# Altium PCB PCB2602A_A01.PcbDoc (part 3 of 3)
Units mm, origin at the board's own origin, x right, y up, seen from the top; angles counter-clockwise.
Board outline 30.4 x 45.4 mm, 8 copper layers (Top Layer, Signal Layer 2, Signal Layer 3, Signal Layer 4, Signal Layer 5, Signal Layer 6, Signal Layer 7, Bottom Layer), stack 1.594 mm thick; 180 components, 124 nets, 679 pads, 487 vias.
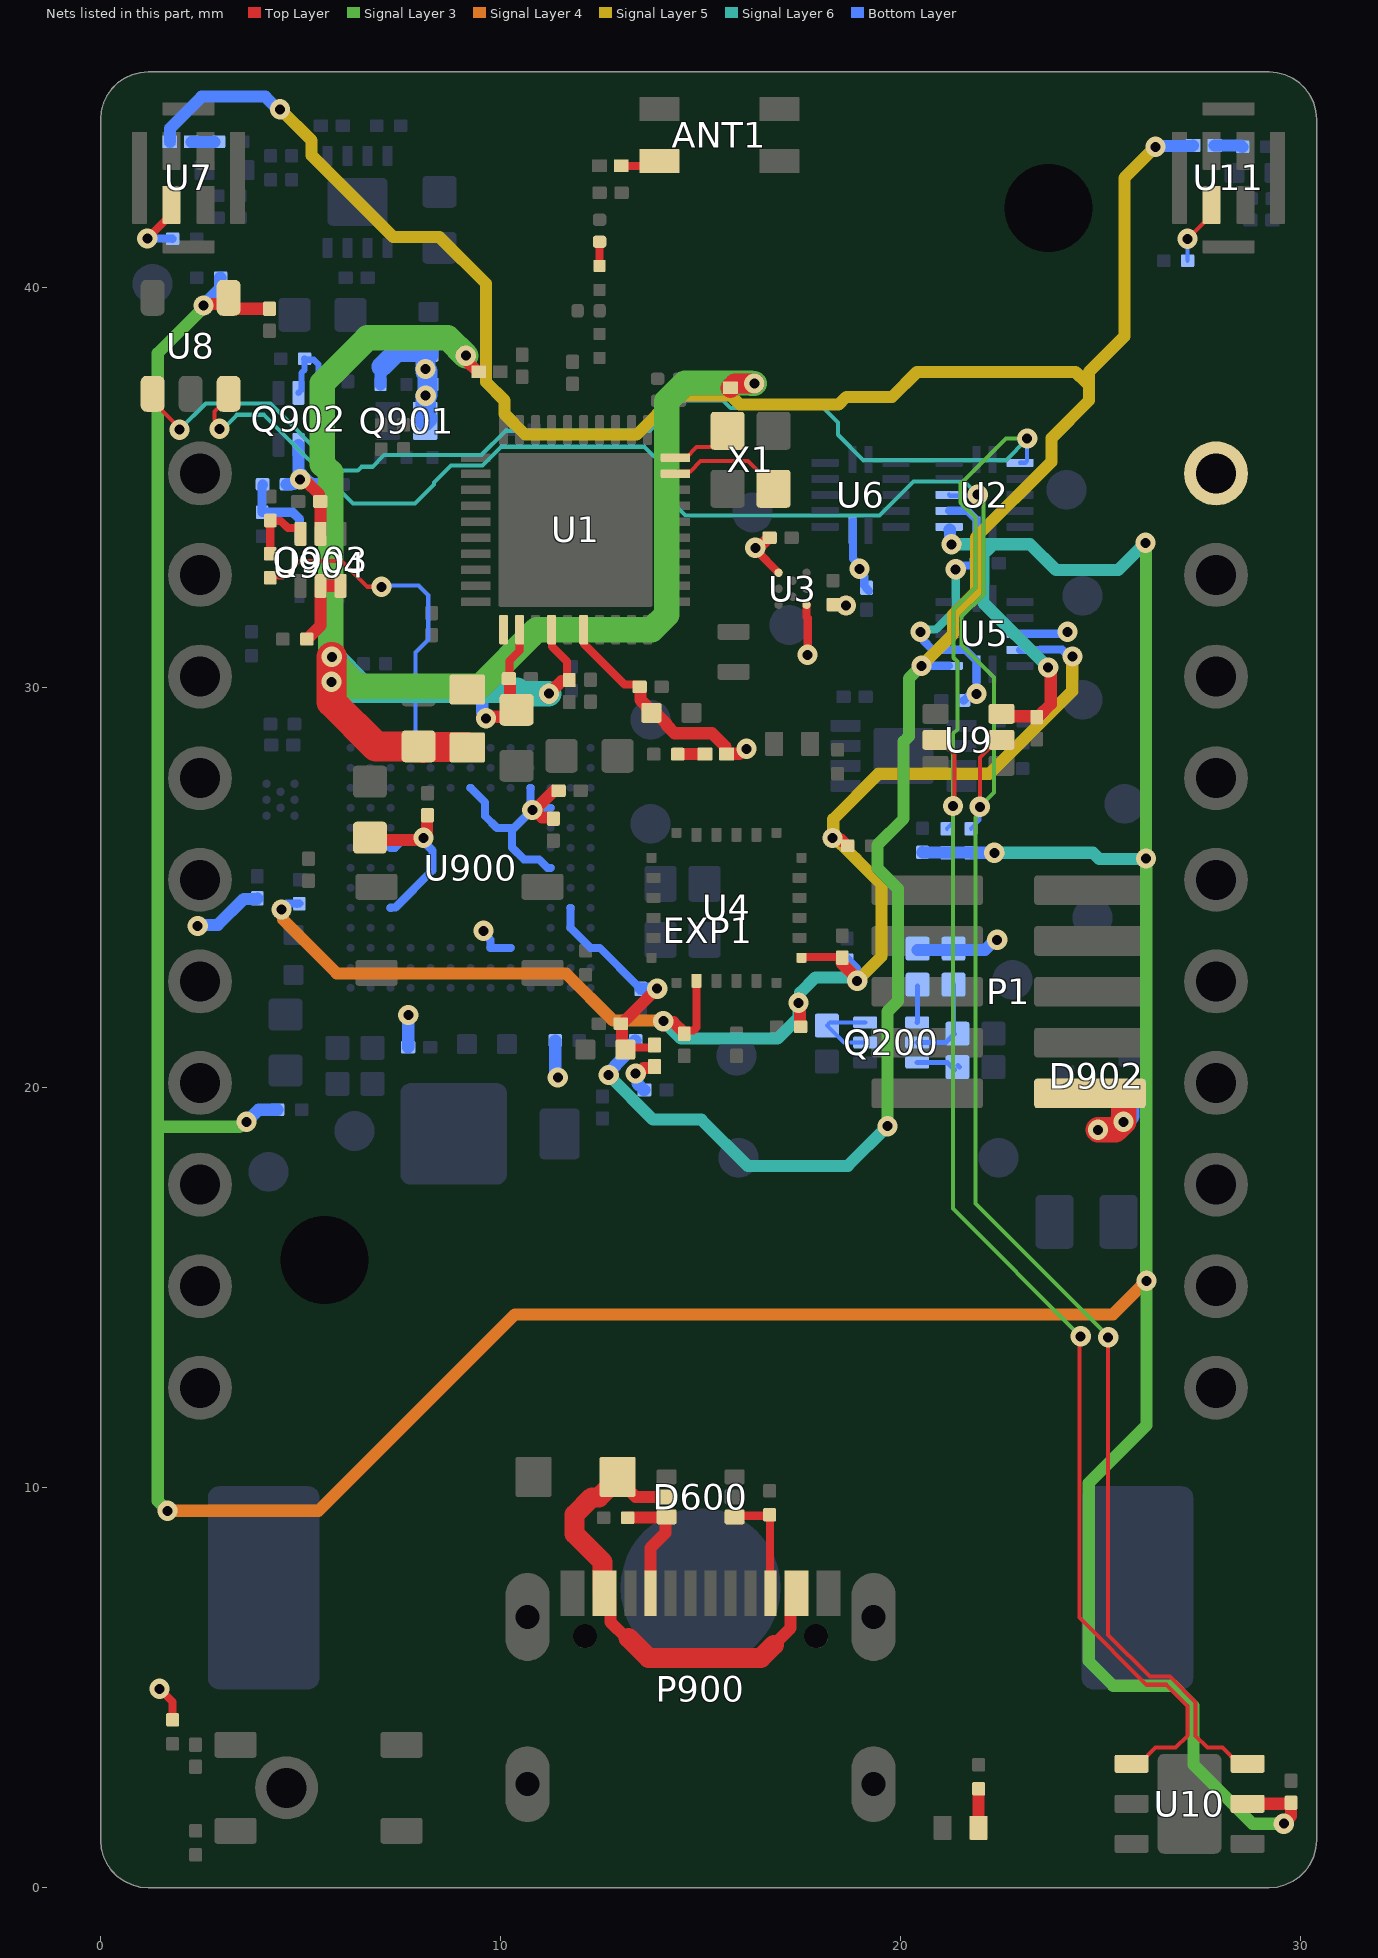
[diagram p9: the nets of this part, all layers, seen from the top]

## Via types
v1: diameter 0.508, hole 0.25, Top Layer to Bottom Layer, tented both sides, 475 vias
v2: diameter 0.5, hole 0.25, Top Layer to Bottom Layer, tented both sides, 12 vias

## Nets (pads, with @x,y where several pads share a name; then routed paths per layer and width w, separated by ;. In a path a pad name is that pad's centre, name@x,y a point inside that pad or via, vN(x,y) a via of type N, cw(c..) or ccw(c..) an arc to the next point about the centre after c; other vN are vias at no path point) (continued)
N17008263: C903.1 C904.1 C905.1 L900.2 U900.M9 U900.M10 U900.N11 | length 6
  Top Layer w0.2: C903.1@13.119,20.956 13.176,21.013 13.793,21.013 L900.2@13.85,21.07
  Top Layer w0.305: C905.1@13.008,21.6 C905.1@13.028,21.6 ; C903.1@13.119,20.956 13.035,21.04 13.035,21.593 C905.1@13.028,21.6 ; v1(13.914,22.477) 13.904,22.477 C905.1@13.028,21.6
  Bottom Layer w0.2: U900.M9@11.75,24.5 U900.M10@11.75,24 U900.N11@12.25,23.5 12.477,23.5 13.426,22.551 13.446,22.551 13.506,22.491 C904.1@13.506,22.471
  Bottom Layer w0.305: C904.1@13.506,22.482 13.514,22.474 13.912,22.474 v1(13.914,22.477)
N17051201: ANT1.1 L9.2 | length 1
  Top Layer w0.2: L9.2@13.015,43.05 13.856,43.05 ANT1.1@13.972,43.166
N17150045: R17.1 U7.1 | length 1.7
  Top Layer w0.2: v1(1.169,41.231) 1.775,41.836 U7.1@1.775,42.075
  Bottom Layer w0.2: v1(1.169,41.231) 1.794,41.231 R17.1@1.8,41.225
N17150219: R24.1 U11.1 | length 1.8
  Top Layer w0.102: v1@27.1,41.15 v1(27.175,41.225) 27.775,41.825 U11.1@27.775,42.075
  Bottom Layer w0.102: R24.1@27.175,40.675 v1(27.175,41.225)
N17150294: L6.2 R15.2 | length 0.6
  Bottom Layer w0.3: L6.2@2.27,43.65 R15.2@2.85,43.65
N17150309: L7.2 R20.2 | length 0.7
  Bottom Layer w0.3: L7.2@27.853,43.558 28.507,43.558 28.54,43.525 R20.2@28.55,43.525
N17151320: L8.2 R6.1 | length 0.7
  Top Layer w0.305: R6.1@14.429,28.341 14.43,28.342 L8.2@15.11,28.343 L8.2@15.11,28.343
N17172364: L3.1 U1.31
N17314136: Q200.5 R206.2 R207.1 | length 2.3
  Bottom Layer w0.125: Q200.5@20.416,21.133 21.133,21.133 R206.2@21.35,21.35 ; R206.2@21.325,21.35 R207.1@21.325,22.58
N17314162: Q200.6 R212.1 | length 1.1
  Bottom Layer w0.125: Q200.6@20.416,20.633 21.167,20.633 R212.1@21.35,20.45 ; R212.1@21.435,20.551 R212.1@21.473,20.514
N17314928: Q200.2 Q200.3 R208.2 | length 2.1
  Bottom Layer w0.102: R208.2@18.158,21.557 18.582,21.133 Q200.2@19.116,21.133 ; R208.2@18.2,21.597 18.2,21.6 18.233,21.633 Q200.3@19.116,21.633
N17328899: Q200.4 R210.1 | length 0.9
  Bottom Layer w0.125: Q200.4@20.416,21.633 20.425,21.641 R210.1@20.425,22.55
N17374949: U1.9 X1.3 | length 2.9
  Top Layer w0.102: U1.9@14.37,35.35 14.429,35.409 14.744,35.409 15.003,35.668 16.182,35.668 16.825,35.025 X1.3@16.825,34.975
N17374973: U1.10 X1.1 | length 1.6
  Top Layer w0.102: U1.10@14.37,35.75 14.63,35.75 14.902,36.022 15.162,36.022 15.322,36.022 X1.1@15.675,36.375
N17389094: C928.1 Q902.2 Q903.2 R916.1 R934.1 | length 3.4
  Top Layer w0.3: v1(4.991,35.209) 5.031,35.169 5.131,35.169 5.463,34.837 5.463,34.666 5.473,34.656 C928.1@5.493,34.656 5.5,34.649 Q903.2@5.5,33.85
  Bottom Layer w0.3: R916.1@4.649,35.087 4.659,35.097 4.841,35.097 4.953,35.209 v1(4.991,35.209) ; Q902.2@4.95,36.075 4.95,35.406 5.05,35.306 v1@5.05,35.25 ; v1@4.994,35.25 v1@5.05,35.25 ; R934.1@5.461,35.085 5.451,35.095 5.261,35.095 5.106,35.25 v1@5.05,35.25
N17389096: R916.2 R917.2 U904.1 | length 2.1
  Bottom Layer w0.229: R916.2@4.069,35.077 4.059,35.087 R916.2@4.049,35.087 4.04,35.077 R917.2@4.04,34.387 4.799,34.387 4.975,34.211 U904.1@4.975,33.825
N17389104: Q902.5 Q902.6 R918.1 | length 2
  Bottom Layer w0.152: Q902.5@4.95,37.375 5.024,37.449 5.024,37.874 5.1,37.95 R918.1@5.1,38.225 ; R918.1@5.09,38.225 R918.1@5.1,38.225 ; R918.1@5.11,38.225 R918.1@5.1,38.225 ; Q902.6@5.45,37.375 5.45,38.075 5.325,38.2 5.125,38.2 R918.1@5.1,38.225
N17433295: CC1.1 L2.2 | length 0.6
  Top Layer w0.2: L2.2@12.475,40.55 CC1.1@12.475,41.15
N17440739: Q903.3 R935.2 R937.1 | length 1.8
  Top Layer w0.203: R935.2@4.242,33.352 4.243,33.353 4.243,34.18 R937.1@4.244,34.181 4.252,34.173 4.506,34.173 4.688,33.991 4.952,33.991 5,33.943 Q903.3@5,33.85
N17440773: Q903.5 Q903.6 R936.1 | length 2
  Top Layer w0.305: R936.1@5.155,31.218 5.163,31.225 5.173,31.225 5.5,31.552 5.5,32.05 Q903.5@5.5,32.55 Q903.6@6,32.55
N17458109: LED900.2 R905.2 | length 1
  Top Layer w0.3: LED900.2@21.95,1.5 R905.2@21.95,2.475
SENSOR_I2C_SCL: R18.2 U2.3 U8.3 U9.5 U10.6 | length 63
  Top Layer w0.102: v1(2.975,36.475) 2.975,36.585 2.85,36.71 2.85,36.907 2.91,36.966 2.912,36.966 3.2,37.254 U8.3@3.2,37.35 3.2,37.172 U8.3@3.057,37.029 ; v1(21.983,27.025) 21.983,28.262 22.421,28.7 U9.5@22.525,28.7 ; v1(25.189,13.76) 25.189,6.323 26.234,5.278 26.734,5.278 27.378,4.634 27.378,3.799 27.675,3.502 28.048,3.502 28.45,3.1 U10.6@28.675,3.1
  Signal Layer 3 w0.102: v1(21.926,34.827) 22.075,34.678 22.075,32.325 21.527,31.777 21.527,31.073 22.341,30.259 22.341,27.383 21.905,26.947 21.905,26.793 21.875,26.762 21.875,17.107 25.189,13.792 v1(25.189,13.76)
  Signal Layer 6 w0.102: v1(2.975,36.475) 3.055,36.475 3.405,36.825 4.091,36.825 6.309,34.607 7.857,34.607 8.331,35.082 8.331,35.131 8.761,35.561 9.552,35.561 10.016,36.025 13.603,36.025 14.1,35.528 14.1,34.82 14.618,34.302 19.473,34.302 20.328,35.156 21.596,35.156 v1(21.926,34.827)
  Bottom Layer w0.102: U2.3@21.215,34.825 21.24,34.8 21.899,34.8 v1(21.926,34.827) ; R18.2@21.758,26.475 21.758,26.485 21.973,26.7 21.975,26.7 21.975,27.017 v1(21.983,27.025)
SENSOR_I2C_SDA: R19.2 U2.8 U8.1 U9.2 U10.1 | length 66.8
  Top Layer w0.102: U8.1@1.3,37.127 U8.1@1.3,37.163 ; U8.1@1.3,37.35 U8.1@1.3,37.163 ; v1(1.975,36.452) 1.975,36.488 U8.1@1.3,37.163 ; U9.2@20.875,28.7 20.979,28.7 21.352,28.327 21.352,27.087 v1(21.31,27.044) ; v1(24.504,13.786) 24.469,13.751 24.469,6.756 26.15,5.075 26.65,5.075 27.175,4.55 27.175,3.8 26.877,3.502 26.377,3.502 25.975,3.1 U10.1@25.775,3.1
  Signal Layer 3 w0.102: v1@21.308,27.088 21.31,27.09 21.31,28.851 21.418,28.959 21.418,30.656 21.324,30.75 21.324,31.959 21.872,32.507 21.872,34.253 21.5,34.625 21.5,35.1 22.631,36.231 v1(23.166,36.231) ; v1(21.31,27.044) 21.308,27.042 21.308,16.982 v1(24.504,13.786)
  Signal Layer 6 w0.102: v1(1.975,36.452) 2.63,37.106 4.244,37.106 5.916,35.434 6.43,35.434 6.521,35.525 6.8,35.525 7.089,35.814 9.517,35.814 10.128,36.425 13.717,36.425 14.477,37.185 15.567,37.185 15.754,36.997 18.078,36.997 18.441,36.634 18.441,36.325 19.079,35.687 22.637,35.687 23.166,36.216 v1(23.166,36.231)
  Bottom Layer w0.102: R19.2@21.158,26.475 21.158,26.485 21.31,26.637 v1(21.31,27.044) ; U2.8@22.985,35.625 23.117,35.625 23.166,35.674 v1(23.166,36.231)
USB_PGOOD: R935.1 U900.E1 | length 8.6
  Top Layer w0.102: R935.1@4.242,32.752 4.558,32.752 4.977,33.17 6.023,33.17 6.669,32.525 v1(7.025,32.525)
  Bottom Layer w0.102: v1(7.025,32.525) 7.055,32.555 7.617,32.555 7.953,32.555 8.191,32.317 8.191,31.194 7.874,30.877 7.874,28.876 U900.E1@8.25,28.5
USBC_CC1: D600.6 P900.A5 R621.2 | length 3
  Top Layer w0.3: R621.2@13.175,9.25 13.185,9.26 D600.6@14.135,9.26 ; P900.A5@13.75,7.36 13.75,8.5 14.125,8.875 14.125,9.25 D600.6@14.135,9.26 ; D600.6@14.15,9.275 D600.6@14.135,9.26
USBC_CC2: D600.1 P900.B5 R620.2 | length 2.9
  Top Layer w0.203: D600.1@15.85,9.275 15.875,9.3 16.725,9.3 R620.2@16.738,9.313 ; R620.2@16.725,9.325 R620.2@16.738,9.313 ; P900.B5@16.75,7.36 16.738,7.372 R620.2@16.738,9.313
USBC_VBUS: D600.5 L901.1 P900.A4_B9 P900.B4_A9 | length 12.1
  Top Layer w0.3: P900.A4_B9@12.6,7.36 12.75,7.21 12.75,6.642 13.142,6.25 13.197,6.25 ; L901.1@12.925,10.275 12.925,10.225 13.375,9.775 D600.5@14.15,9.775 ; 16.837,6.075 17.25,6.488 17.25,7.21 P900.B4_A9@17.4,7.36
  Top Layer w0.5: P900.A4_B9@12.6,7.36 12.55,7.41 12.55,8.15 11.85,8.85 11.85,9.329 12.283,9.762 12.462,9.762 L901.1@12.925,10.225 ; 13.197,6.25 13.697,5.75 16.512,5.75 16.837,6.075
VDCDC: C7.1 C13.1 L3.2 L4.1 L5.1 U1.34 | length 44.7
  Top Layer w0.203: U1.34@11.275,31.455 11.283,31.447 11.283,31.03 11.66,30.653 11.66,30.252 C13.1@11.703,30.209
  Top Layer w0.3: v1@9.168,38.301 v1(9.131,38.301) 9.17,38.261 9.17,38.157 9.427,37.9 L5.1@9.452,37.9
  Top Layer w0.305: v1(11.209,29.853) 11.522,30.166 11.711,30.166 11.719,30.173 C13.1@11.719,30.193
  Top Layer w0.5: L4.1@15.745,37.5 15.85,37.605 v1(16.344,37.607) v1(16.344,37.607)
  Top Layer w0.75: v1(5.78,30.775) 5.775,30.77 v1(5.775,30.15) 5.775,29.643 6.888,28.53 7.9,28.53 7.903,28.527 C7.1@7.903,28.51 ; C7.1@8.065,28.5 8.09,28.525 L3.2@9.175,28.525
  Signal Layer 3 w0.635: v1(5.775,30.15) 5.889,30.035 6.426,30.035 ; v1(9.131,38.301) 8.685,38.747 6.672,38.747 5.544,37.619 5.544,35.593 5.752,35.385 5.752,30.803 v1(5.78,30.775) 5.78,30.682 6.426,30.035 ; v1(16.344,37.607) 16.273,37.607 16.26,37.62 14.61,37.62 14.15,37.16 14.15,31.822 13.778,31.45 10.9,31.45 9.486,30.035 6.426,30.035
  Signal Layer 6 w0.635: v1@5.78,30.402 v1@5.845,30.336 ; v1(11.209,29.853) 10.497,29.853 10.416,29.934 6.55,29.934 ; 6.55,29.934 5.991,29.934 v1(5.775,30.15) 5.775,30.77 v1(5.78,30.775) 6.55,30.005 6.55,29.934
VDD_IMU: C26.1 C27.1 C39.1 R13.1 R14.1 R932.2 U4.8 U4.13 U5.11 | length 37.3
  Top Layer w0.2: C27.1@14.592,21.35 14.592,21.37 14.652,21.43 14.822,21.43 14.9,21.508 U4.8@14.9,22.53 ; U4.13@17.525,23.25 17.54,23.265 C26.1@18.544,23.265
  Top Layer w0.3: v1(14.069,21.664) 14.092,21.641 14.321,21.641 C27.1@14.592,21.37 ; v1(17.45,22.125) 17.48,22.095 17.48,21.535 17.49,21.525 R14.1@17.5,21.525 ; v1(18.299,26.245) 18.339,26.205 18.51,26.205 18.655,26.06 18.665,26.06 R13.1@18.675,26.05 ; C26.1@18.544,23.253 18.544,23.256 18.525,23.275 18.525,23.252 18.525,23.121 18.914,22.731 v1(18.914,22.675)
  Signal Layer 4 w0.3: v1(4.523,24.457) 4.563,24.418 4.563,24.201 5.904,22.86 11.63,22.86 12.809,21.681 14.052,21.681 v1(14.069,21.664)
  Signal Layer 5 w0.3: v1(18.299,26.245) 18.355,26.245 18.501,26.099 18.509,26.099 18.88,25.728 19.518,25.09 19.518,23.279 v1(18.914,22.675)
  Signal Layer 5 w0.305: v1(18.299,26.245) 18.315,26.261 18.315,26.715 19.45,27.85 22.225,27.85 24.292,29.917 24.292,30.773 v1(24.3,30.781)
  Signal Layer 6 w0.3: v1(14.069,21.664) 14.506,21.227 16.922,21.227 17.45,21.755 v1(17.45,22.125) 17.49,22.165 17.49,22.377 17.874,22.761 18.772,22.761 18.858,22.675 v1(18.914,22.675)
  Bottom Layer w0.2: v1(4.523,24.457) 4.667,24.601 R932.2@4.914,24.601 ; R932.2@4.91,24.597 R932.2@4.914,24.601 ; R932.2@4.97,24.601 R932.2@4.914,24.601 ; U5.11@22.985,30.95 23.491,30.95 23.501,30.96 24.038,30.96 24.217,30.781 v1(24.3,30.781)
  Bottom Layer w0.3: C39.1@18.662,23.181 18.662,23.161 18.875,22.949 18.875,22.715 v1(18.914,22.675)
VDD_MIC: L6.1 L7.1 R930.2 U5.1 | length 68.8
  Signal Layer 3 w0.3: v1(19.673,19.04) 19.673,21.906 19.937,22.169 19.937,24.979 19.425,25.491 19.425,26.075 20.077,26.727 20.077,28.655 20.206,28.783 20.206,30.231 v1(20.525,30.55)
  Signal Layer 5 w0.3: v1(4.488,44.463) 4.496,44.463 5.275,43.684 5.275,43.31 7.316,41.269 8.471,41.269 9.639,40.101 9.639,37.642 10.1,37.18 10.1,36.843 10.614,36.329 13.4,36.329 14.38,37.309 15.748,37.309 15.976,37.081 18.453,37.081 18.647,37.275 19.79,37.275 20.41,37.895 24.375,37.895 24.657,37.612 24.708,37.612 ; v1(20.525,30.55) 21.308,31.333 21.308,31.829 21.884,32.405 21.884,33.759 23.775,35.65 23.775,36.243 24.708,37.176 24.708,37.612 ; v1(26.375,43.525) 25.6,42.75 25.6,38.787 24.708,37.895 24.708,37.612
  Signal Layer 6 w0.3: v1(12.702,20.321) 12.702,20.313 13.81,19.205 15.017,19.205 16.172,18.05 18.683,18.05 v1(19.673,19.04)
  Bottom Layer w0.203: v1(20.525,30.55) 20.527,30.552 21.214,30.552 U5.1@21.215,30.55
  Bottom Layer w0.3: L6.1@1.73,43.65 1.73,43.98 2.527,44.777 4.117,44.777 4.432,44.463 v1(4.488,44.463) ; v1(12.702,20.321) 12.702,20.377 12.873,20.548 12.873,20.564 13.197,20.888 13.197,21.017 13.365,21.185 R930.2@13.375,21.185 ; v1(26.375,43.525) 26.398,43.548 27.303,43.548 L7.1@27.313,43.558
VDD_SENSOR: C35.1 C36.1 C37.1 R18.1 R19.1 R22.1 R23.1 R931.2 U2.1 U8.4 U9.6 U10.5 | length 119.1
  Top Layer w0.305: v1(2.572,39.555) 2.611,39.594 3.052,39.594 3.066,39.608 3.066,39.616 U8.4@3.2,39.75 3.2,39.623 3.348,39.475 C36.1@4.225,39.475 ; U9.6@22.525,29.35 22.585,29.29 C35.1@23.41,29.29 ; C35.1@23.404,29.264 23.404,29.284 C35.1@23.41,29.29 ; v1(23.69,30.505) 23.69,30.45 23.756,30.384 23.756,29.587 C35.1@23.46,29.292 ; U10.5@28.675,2.1 C37.1@29.737,2.1 ; v1(29.583,1.603) 29.583,1.616 29.761,1.794 29.761,2.076 C37.1@29.737,2.1 ; C37.1@29.761,2.126 29.761,2.108 29.753,2.1 C37.1@29.737,2.1 ; C35.1@23.41,29.29 23.458,29.29 C35.1@23.46,29.292 ; C35.1@23.41,29.29 23.412,29.292 C35.1@23.46,29.292
  Signal Layer 3 w0.305: v1(1.675,9.425) 1.432,9.668 1.432,19.025 ; v1(2.572,39.555) 2.572,39.503 1.432,38.364 1.432,19.025 ; v1(3.65,19.15) 3.595,19.15 3.47,19.025 1.432,19.025 ; v1(26.125,33.625) 26.137,33.613 v1(26.137,25.73) 26.143,25.723 26.143,15.182 v1(26.15,15.175) 26.15,11.564 24.703,10.117 24.703,5.666 25.319,5.05 26.825,5.05 27.325,4.55 27.325,3.075 28.797,1.603 v1(29.583,1.603)
  Signal Layer 4 w0.305: v1(1.675,9.425) 5.45,9.425 10.36,14.335 25.31,14.335 v1(26.15,15.175)
  Signal Layer 6 w0.305: v1(21.275,33.586) 22.014,33.586 ; 22.169,33.431 22.325,33.586 ; v1(22.344,25.875) 24.81,25.875 24.968,25.717 26.123,25.717 v1(26.137,25.73) ; v1(23.69,30.505) 22.075,32.12 22.075,33.525 22.014,33.586 ; v1(26.125,33.625) 25.442,32.942 23.883,32.942 23.239,33.586 22.325,33.586 ; 22.014,33.586 22.325,33.586
  Bottom Layer w0.305: v1(2.572,39.555) 2.982,39.966 2.982,40.242 2.99,40.25 R23.1@3,40.25 ; v1(3.65,19.15) 3.95,19.45 R931.2@4.425,19.45 ; R22.1@20.549,25.887 20.555,25.881 21.752,25.881 R18.1@21.758,25.875 v1(22.344,25.875) ; U2.1@21.23,33.95 21.236,33.944 21.236,33.625 v1(21.275,33.586)
VMCU: C8.1 C9.1 C14.1 C15.1 C22.1 C23.1 C24.1 C25.1 C907.1 C908.1 C909.1 C910.1 C911.1 C920.1 C924.1 C925.1 C926.1 D902.2 EXP1.2 L8.1 L900.1 P1.1 Q901.4 Q901.6 Q901.7 R12.1 R25.1 R207.2 R210.2 R901.2 U1.32 U1.36 U2.2 U2.14 U3.A1 U3.E3 U5.2 U5.10 U5.14 U6.14 U900.C6 U900.C9 U900.G3 U900.H11 U900.J11 U900.K3 U900.L4 U900.L7 | length 50.8
  Top Layer w0.203: v1(1.475,4.975) 1.8,4.65 R25.1@1.8,4.2 ; C9.1@10.208,30.23 10.225,30.247 10.225,30.675 10.475,30.925 U1.32@10.475,31.455 ; U1.36@12.07,31.45 12.083,31.436 12.083,31.095 13.095,30.083 13.417,30.083 C15.1@13.475,30.025 ; v1(16.369,33.5) 16.369,33.458 U3.A1@16.95,32.875 U3.A1@16.95,32.875 ; U3.E3@17.66,32.066 17.652,32.075 U3.E3@17.65,32.075 17.65,31.769 17.679,31.74 17.679,30.829 v1(17.675,30.825) ; R12.1@18.339,32.071 18.342,32.068 18.623,32.068 v1(18.634,32.057)
  Top Layer w0.3: C907.1@6.811,26.249 6.865,26.196 7.963,26.196 8.017,26.25 v1(8.073,26.25) ; v1@8.075,26.25 8.075,26.306 8.164,26.395 8.164,26.803 C924.1@8.174,26.813 ; v1(10.794,26.943) 10.845,26.943 11.03,26.759 11.311,26.759 11.321,26.749 C925.1@11.321,26.729 ; v1@10.839,26.956 10.863,26.956 11.322,27.415 11.44,27.415 C926.1@11.45,27.425 ; v1(13.379,20.355) 13.435,20.355 13.575,20.495 13.84,20.495 13.85,20.505 L900.1@13.85,20.53 ; R12.1@18.312,32.08 18.321,32.071 R12.1@18.339,32.071
  Top Layer w0.305: v1(9.638,29.235) 9.677,29.274 10.224,29.274 C8.1@10.4,29.45 10.236,29.614 10.236,30.223 10.228,30.23 C9.1@10.208,30.23 ; C15.1@13.475,30.025 13.492,30.025 13.499,30.017 13.499,29.696 13.673,29.523 13.673,29.473 C14.1@13.77,29.375 13.87,29.375 14.145,29.1 14.145,29.07 14.351,28.864 15.284,28.864 15.618,28.531 15.618,28.376 L8.1@15.65,28.343 15.658,28.351 15.972,28.351 16.095,28.474 v1(16.146,28.474) ; v1(16.369,33.5) 16.407,33.539 16.494,33.539 16.705,33.75 C25.1@16.725,33.75
  Top Layer w0.635: v1(24.937,18.949) 25.374,18.949 v1(25.575,19.15) 25.575,19.807 P1.1@25.522,19.86
  Signal Layer 6 w0.203: v1(20.5,31.4) 20.558,31.458 20.883,31.458 21.378,31.953 v1(21.378,32.962)
  Bottom Layer w0.18: C24.1@19.14,32.49 C24.1@19.15,32.5
  Bottom Layer w0.2: U900.C9@7.25,24.5 7.26,24.51 7.373,24.51 8.3,25.436 8.3,25.933 8.149,26.084 8.149,26.134 v1@8.08,26.203 ; U900.C6@7.25,26 7.364,26 7.566,26.203 8.026,26.203 v1(8.073,26.25) ; U900.G3@9.25,27.5 9.617,27.133 9.617,26.79 9.915,26.492 10.335,26.492 ; v1(9.575,23.925) 9.575,23.87 9.75,23.695 U900.H11@9.75,23.5 U900.J11@10.25,23.5 ; U900.K3@10.75,27.5 10.75,27.064 10.833,26.982 10.851,27 U900.L4@11.25,27 ; v1(10.794,26.943) 10.787,26.943 10.335,26.492 ; U900.L7@11.25,25.5 11.175,25.5 10.964,25.712 10.584,25.712 10.287,26.009 10.287,26.443 10.335,26.492
  Bottom Layer w0.203: v1(8.124,37.97) 8.124,37.901 8.124,37.888 8.175,37.837 8.252,37.76 8.252,37.636 Q901.6@8.3,37.587 ; U6.14@18.807,34.179 18.807,33.225 18.975,33.057 v1(18.975,32.975) 18.975,32.892 19.092,32.776 19.092,32.558 C24.1@19.15,32.5 C24.1@19.15,32.48 ; C24.1@19.14,32.49 C24.1@19.15,32.48 ; C24.1@19.208,32.422 C24.1@19.15,32.48 ; v1(20.5,31.4) 20.558,31.342 20.558,31.194 20.802,30.95 21.625,30.95 21.9,30.675 U5.14@21.9,30.465 v1(21.9,29.85) 21.842,29.792 21.694,29.792 21.587,29.685 C23.1@21.567,29.685 ; U2.2@21.215,34.425 21.675,34.425 21.9,34.2 U2.14@21.9,33.94 21.902,33.938 21.902,33.587 21.909,33.579 C22.1@21.909,33.115 21.85,33.056 21.556,33.056 21.461,32.962 v1(21.378,32.962) ; U5.10@22.985,31.35 22.987,31.352 24.127,31.352 v1(24.175,31.4)
  Bottom Layer w0.3: v1(2.427,24.046) 2.455,24.073 2.933,24.073 3.581,24.721 3.909,24.721 3.919,24.731 C910.1@3.919,24.736 ; Q901.4@7,37.587 7,38 7.025,38.025 ; v1(13.379,20.355) 13.418,20.315 13.418,20.107 13.578,19.947 C909.1@13.598,19.947 ; R210.2@20.425,23.45 22.113,23.45 22.359,23.697 v1(22.416,23.697)
  Bottom Layer w0.305: C911.1@7.689,21.014 7.692,21.017 7.692,21.814 v1(7.695,21.817) ; C908.1@9.542,30.048 9.542,29.387 9.638,29.29 v1(9.638,29.235) ; R901.2@11.368,21.182 11.368,20.377 11.431,20.313 v1(11.431,20.258) ; v1(13.379,20.355) v1@13.379,20.41
  Bottom Layer w0.508: 7.025,38.025 7.4,38.4 C920.1@8.2,38.4 8.2,38.33 8.124,38.254 v1(8.124,37.97) 8.175,37.92 v1@8.175,37.85 ; Q901.7@8.116,36.675 Q901.7@8.129,36.687 ; v1@8.124,37.901 v1@8.175,37.85 ; Q901.7@8.169,36.727 Q901.7@8.129,36.687 ; v1(24.937,18.949) 25.009,19.021 25.446,19.021 25.725,19.3 D902.2@25.725,19.8 ; Q901.7@8.129,36.687 v1(8.129,37.302) 8.156,37.302 8.175,37.322 8.175,37.837 v1@8.175,37.85
pads on no net: M901.1 M902.1 P900.1 P900.2 P900.A8 P900.B8 U2.10 U2.11 U3.C1 U4.1 U4.2 U4.3 U4.4 U4.5 U4.6 U4.7 U4.14 U4.15 U4.16 U4.17 U4.19 U4.20 U4.21 U9.4 U10.3 U10.4 U10.7 U900.A5 U900.B4 U900.B5 U900.B6 U900.B7 U900.B8 U900.B9 U900.B11 U900.C4 U900.C7 U900.D2 U900.D13 U900.E2 U900.E11 U900.E12 U900.E13 U900.F1 U900.F2 U900.F3 U900.F11 U900.F12 U900.G1 U900.G2 U900.G12 U900.H1 U900.H2 U900.J1 U900.J2 U900.K1 U900.K2 U900.K13 U900.L3 U900.L11 U900.L12 U900.L13 U900.M2 U900.M3 U900.M4 U900.M5 U900.M6 U900.M12 U900.M13 U900.N3 U900.N4 U900.N5 U900.N6 U900.N7 U901.C1 U902.8 U903.9 U904.3

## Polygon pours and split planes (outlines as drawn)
VMCU on Signal Layer 7 "VMCU_L7" (solid, remove dead copper, pour order 47): 0.597,1.203 0.597,44.189 cw(c1.212,44.189) 1.212,44.804 12.209,44.804 19.709,44.804 29.184,44.804 cw(c29.184,44.183) 29.806,44.183 29.806,1.206 cw(c29.195,1.205) 29.194,0.594 1.206,0.594 cw(c1.206,1.203)
GND on Signal Layer 7 "GND_L07_P018" (solid, remove dead copper, pour order 18): 9.713,44.804 9.713,32.2 10.139,31.774 13.729,31.774 14.076,32.121 14.076,37.104 15.004,38.032 17.869,38.032 19.522,39.685 19.522,44.804
GND on Bottom Layer "GND_L8" (solid, remove dead copper, pour order 16): 0.597,1.203 0.597,41.6 0.597,44.804 29.196,44.804 cw(c29.196,44.195) 29.806,44.194 29.806,7.4 29.806,3.6 29.806,1.206 cw(c29.202,1.205) 29.202,0.602 1.198,0.602 cw(c1.198,1.203)
GND on Signal Layer 3 "GND_L3" (solid, remove dead copper, pour order 20): 0.597,1.203 0.597,44.197 cw(c1.204,44.197) 1.204,44.804 12.2,44.804 19.7,44.804 29.196,44.804 cw(c29.196,44.195) 29.806,44.194 29.806,1.206 cw(c29.194,1.205) 29.194,0.594 1.206,0.594 cw(c1.206,1.203)
GND on Signal Layer 2 "GND_L2" (solid, remove dead copper, pour order 24): 0.597,1.203 0.597,44.197 cw(c1.204,44.197) 1.204,44.804 12.2,44.804 19.7,44.804 29.196,44.804 cw(c29.196,44.197) 29.803,44.197 29.805,1.214 cw(c29.195,1.205) 29.195,0.595 1.205,0.595 cw(c1.205,1.203)
GND on Signal Layer 4 "GND_L4" (solid, remove dead copper, pour order 38): 0.597,1.203 0.597,44.201 cw(c1.2,44.201) 1.2,44.804 12.209,44.804 19.709,44.804 29.196,44.804 cw(c29.196,44.194) 29.806,44.194 29.806,1.206 cw(c29.194,1.205) 29.194,0.594 1.206,0.594 cw(c1.206,1.203)
GND on Signal Layer 5 "GND_L5" (solid, remove dead copper, pour order 40): 0.597,1.203 0.597,44.189 cw(c1.212,44.189) 1.212,44.804 12.209,44.804 19.709,44.804 29.184,44.804 cw(c29.184,44.183) 29.806,44.183 29.806,1.206 cw(c29.195,1.205) 29.194,0.594 1.206,0.594 cw(c1.206,1.203)
GND on Signal Layer 6 "GND_L6" (solid, remove dead copper, pour order 44): 0.597,1.203 0.597,44.189 cw(c1.212,44.189) 1.212,44.804 12.209,44.804 19.709,44.804 29.184,44.804 cw(c29.184,44.183) 29.806,44.183 29.806,1.206 cw(c29.195,1.205) 29.194,0.594 1.206,0.594 cw(c1.206,1.203)
GND on Top Layer "GND_L1" (solid, remove dead copper, pour order 46): 0.597,1.203 0.597,41.6 0.597,44.804 29.196,44.804 cw(c29.196,44.195) 29.806,44.194 29.806,7.4 29.806,3.6 29.806,1.206 cw(c29.202,1.205) 29.202,0.602 1.198,0.602 cw(c1.198,1.203)

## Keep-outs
Bottom Layer:
  circle w0.1: c26.05,22 r0.5
  circle w0.1: c23.65,26.75 r0.5
  circle w0.1: c17.22,29.05 r0.5
  circle w0.1: c14.69,31.53 r0.5
  circle w0.1: c13.8,33.9 r0.5
  circle w0.1: c1.54,10.95 r0.5
  circle w0.1: c22.045,42.635 r0.3
  region: 0.2,6.25 2.2,6.25 2.2,8.15 0.2,8.15
  region: 28.2,6.25 30.2,6.25 30.2,8.15 28.2,8.15
  region: 28.2,36.85 30.2,36.85 30.2,38.75 28.2,38.75
  region: 0.2,36.85 2.2,36.85 2.2,38.75 0.2,38.75
Keep-Out Layer:
  region: 24.35,0.7 ccw(c24.35,1.1) 24.75,1.1 24.75,3.85 26.35,3.85 ccw(c26.35,4.25) 26.75,4.25 ccw(c26.35,4.25) 26.35,4.65 24.35,4.65 ccw(c24.35,4.25) 23.95,4.25 23.95,1.1 ccw(c24.35,1.1)
  region: 28.35,4.65 29.25,4.65 cw(c29.25,4.25) 29.65,4.25 cw(c29.25,4.25) 29.25,3.85 28.35,3.85 cw(c28.35,4.25) 27.95,4.25 cw(c28.35,4.25)

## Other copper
Top Layer:
  rectangle net GND: 13.577,37.623 14.745,38.12
  rectangle net GND: 10.124,38.333 10.95,38.793
  region: 27.141,8.575 cw(c27.141,6.941) 28.775,6.941 cw(c27.209,6.941) 27.209,5.375 cw(c27.209,7.009) 25.575,7.009 cw(c27.141,7.009)
  pour cut-out: 19.9,0 19.9,7.5 cw(c20.9,7.5) 20.9,8.5 30.4,8.5 30.4,1.189 cw(c29.211,1.189) 29.211,0
  region net GND: 11.45,37.983 11.45,38.75 11.911,38.289 11.911,37.983
  pour cut-out: 12.889,38.672 12.889,36.622 12.025,36.622 12.025,38.175 11.1,39.1 11.1,39.75 12.038,40.688 12.038,43.308 12.217,43.487 13.467,43.487 13.467,42.538 12.889,42.538 12.889,40.825
  region net GND: 12.095,39.016 12.095,39.826 11.959,39.962 11.665,39.962 11.292,39.589 11.292,39.258 11.688,38.862 11.941,38.862
  pour cut-out: 17.059,30.775 17.101,30.732 17.329,30.732 17.329,30.918 17.303,30.892 17.037,30.892
  pour cut-out: 26.056,21.925 26.056,21.605 25.855,21.605 25.875,21.625 25.875,21.975 26.006,21.975
  pour cut-out: 26.056,24.465 26.056,24.145 25.855,24.145 25.85,24.15 25.85,24.475 25.86,24.465
  pour cut-out: 17.178,27.825 17.412,28.058 17.412,28.323 17.575,28.16 17.575,27.836 17.346,27.607 17.253,27.7 17.253,27.768
  pour cut-out: 18.125,36.225 18.1,36.225 17.805,35.93 17.805,36.073 17.848,36.073 17.975,36.2
  pour cut-out: 16.646,37.506 16.55,37.41 16.55,37 16.475,37 16.554,37.079 16.554,37.347
  pour cut-out: 6.564,35.779 6.763,35.779 6.755,35.787 6.755,35.832 6.616,35.832 6.576,35.872
  pour cut-out: 5.887,33.446 5.9,33.433 5.9,33.3 5.8,33.3 5.833,33.333 5.833,33.456
  pour cut-out: 8.074,31.517 8.074,31.241 8.01,31.177 7.862,31.325 7.834,31.325 8.021,31.512
  pour cut-out: 4.737,29.856 4.743,29.85 5.325,29.85 5.325,29.925 5.308,29.942 4.701,29.942 4.749,29.894 4.749,29.763
  pour cut-out: 21.305,29.163 22.095,29.163 22.095,29.111 22.108,29.098 21.292,29.098 21.292,29.15
  pour cut-out: 7.375,31.925 7.875,31.925 7.875,31.625 7.375,31.625
  pour cut-out: 14.5,23.35 14.5,25.65 16.8,25.65 16.8,23.35
  pour cut-out: 7.275,27.9 10.95,27.9 10.95,30.275 10.65,30.575 10.65,31.975 9,31.975 7.275,30.25
  pour cut-out: 12.9,32 15.925,32 15.925,30.275 12.9,30.275
  region net N17172364: 8.712,29.591 8.712,30.81 9.727,31.825 10.25,31.825 10.25,30.988 9.728,30.988 9.728,29.591
  region net GND: 13.472,44.804 12.85,44.804 12.85,43.979 13.472,43.979
  pour cut-out: 17.475,45.405 17.475,38.725 13.475,38.725 13.475,45.405
  pour cut-out: 15.658,37.008 18.263,37.008 18.263,36.1 17.805,36.1 17.806,34.29 14.6,34.29 14.6,35.95
Signal Layer 2:
  pour cut-out: 19.9,0 19.9,7.5 cw(c20.9,7.5) 20.9,8.5 30.4,8.5 30.4,1.189 cw(c29.211,1.189) 29.211,0
  pour cut-out: 17.472,45.391 17.472,38.711 13.472,38.711 13.472,45.391
Signal Layer 3:
  pour cut-out: 19.9,0 19.9,7.5 cw(c20.9,7.5) 20.9,8.5 30.4,8.5 30.4,1.189 cw(c29.211,1.189) 29.211,0
  pour cut-out: 1.854,9.736 1.865,9.725 2.325,9.725 2.325,9.775 2.2,9.9 2.175,9.875 1.625,9.875
  pour cut-out: 8.725,33.766 8.661,33.702 8.661,33.104 7.858,33.104 7.371,32.618 7.109,32.88 7.109,32.964 7.695,32.964 8.546,33.814
  pour cut-out: 6.15,32.75 6.153,32.753 6.475,32.753 6.475,32.6 6.425,32.65 6.125,32.65 6.125,32.775
  pour cut-out: 4.95,32.675 5.35,32.675 5.375,32.7 5.475,32.6 5.475,32.575 4.925,32.575 4.875,32.525
  pour cut-out: 4.1,28.475 4.725,28.475 4.725,28.518 4.668,28.575 4.1,28.575
  pour cut-out: 4.661,24.759 5.394,24.759 5.394,24.678 5.382,24.666 5.373,24.675 4.65,24.675 4.65,24.77
  pour cut-out: 5.833,25.656 6.319,25.656 6.325,25.65 6.275,25.6 6.275,25.575 5.915,25.575
  pour cut-out: 12.678,19.507 12.65,19.48 12.65,18.825 12.488,18.825 12.443,18.87 12.548,18.975 12.548,19.507
  pour cut-out: 5.66,27.723 5.737,27.8 6.325,27.8 6.325,27.9 6.3,27.925 5.775,27.925 5.675,27.825
  pour cut-out: 18.717,18.863 18.731,18.85 19.478,18.85 19.375,18.748 19.26,18.863
  pour cut-out: 19.648,18.104 20.213,18.104 20.278,18.17 20.278,18.355 19.766,18.355 19.738,18.383
  pour cut-out: 20.307,36.547 21.068,36.547 21.075,36.555 21.075,36.442 20.983,36.35 20.917,36.416 20.439,36.416
  pour cut-out: 20.871,30.457 20.879,30.45 21.325,30.45 21.325,30.53 21.263,30.592 21.221,30.55 20.884,30.55
  pour cut-out: 17.1,32.975 17.107,32.982 18.004,32.982 18.004,32.931 18.039,32.896 17.969,32.825 16.975,32.825 17.1,32.95
  pour cut-out: 14.73,31.361 15.136,31.361 15.175,31.4 15.175,31.525 14.829,31.525 14.775,31.471
  pour cut-out: 17.472,45.391 17.472,38.711 13.472,38.711 13.472,45.391
Signal Layer 4:
  pour cut-out: 19.9,0 19.9,7.5 cw(c20.9,7.5) 20.9,8.5 30.4,8.5 30.4,1.189 cw(c29.211,1.189) 29.211,0
  pour cut-out: 15.06,21.451 15.674,21.451 15.575,21.55 15.525,21.5 15.024,21.5 15.026,21.502
  pour cut-out: 15.384,32.136 15.4,32.12 15.4,31.675 15.45,31.625 15.475,31.65 15.475,31.994 15.42,32.049
  pour cut-out: 18.649,26.17 18.585,26.106 18.585,25.22 18.716,25.22 18.785,25.288 18.785,26.212
  pour cut-out: 15.258,17.709 15.258,17.533 15.225,17.5 15.2,17.525 15.074,17.525
  pour cut-out: 9.814,20.863 10.662,20.862 10.725,20.925 9.573,20.925 9.511,20.863
  pour cut-out: 8.355,24.349 8.895,24.888 8.895,24.545 8.642,24.292 8.429,24.292
  pour cut-out: 4.505,23.016 4.769,23.016 4.824,23.072 4.514,23.072 4.46,23.126
  pour cut-out: 6.975,22.45 6.975,22.12 6.98,22.125 7.2,22.125 7.2,22.375 7.05,22.525
  pour cut-out: 2.772,24.345 3.545,24.345 3.55,24.35 3.525,24.375 3.525,24.45 2.993,24.45 2.906,24.363 2.833,24.363
  pour cut-out: 4.918,28.526 4.866,28.475 4.025,28.475 4.025,28.525 4.05,28.55 4.074,28.526
  pour cut-out: 7.692,31.802 7.692,31.723 7.354,31.386 7.328,31.412 7.328,31.692 7.531,31.895
  pour cut-out: 3.1,37.55 3.1,36.775 3.05,36.725 2.9,36.875 2.9,37.55 2.95,37.6 3.075,37.6
  pour cut-out: 8.191,35.566 8.609,35.984 8.609,35.91 8.585,35.91 8.184,35.509 8.127,35.566
  pour cut-out: 10.945,36.034 10.929,36.05 10.025,36.05 10.025,36.175 10.121,36.079 10.836,36.079
  pour cut-out: 5.5,39.8 5.872,39.8 5.908,39.836 5.918,39.826 5.918,39.762 5.837,39.762 5.687,39.612
  pour cut-out: 17.472,45.391 17.472,38.711 13.472,38.711 13.472,45.391
Signal Layer 7:
  pour cut-out: 19.9,0 19.9,7.5 cw(c20.9,7.5) 20.9,8.5 30.4,8.5 30.4,1.189 cw(c29.211,1.189) 29.211,0
  pour cut-out: 17.472,45.391 17.472,38.711 13.472,38.711 13.472,45.391
Signal Layer 5:
  pour cut-out: 19.9,0 19.9,7.5 cw(c20.9,7.5) 20.9,8.5 30.4,8.5 30.4,1.189 cw(c29.211,1.189) 29.211,0
  pour cut-out: 20.473,32.335 20.5,32.307 20.5,31.759 20.581,31.759 20.593,31.746 20.634,31.787 20.634,32.242
  pour cut-out: 18.871,31.803 18.871,31.529 18.789,31.447 18.771,31.447 18.771,31.704 18.814,31.746
  pour cut-out: 14.464,29.801 14.126,29.801 14.125,29.8 14.125,29.825 14.366,29.825 14.429,29.888 14.464,29.852
  pour cut-out: 18.945,31.878 18.846,31.778 18.846,31.714 18.814,31.746 18.871,31.803 18.888,31.803
  pour cut-out: 16.701,29.896 16.69,29.885 16.69,28.935 16.71,28.935 16.8,29.025 16.701,29.124 16.701,30.051 16.811,29.941
  pour cut-out: 22.175,37.675 22.205,37.645 22.205,36.729 22.096,36.729 22,36.825 22.075,36.901 22.075,37.725
  pour cut-out: 23.956,35.469 23.956,34.406 23.954,34.404 23.582,34.775 23.525,34.775 23.525,35.05 23.85,35.375
  pour cut-out: 12.596,25.011 12.56,24.975 12.25,24.975 12.25,24.95 12.254,24.954 12.521,24.954
  pour cut-out: 3.929,9.747 3.578,9.747 3.554,9.771 3.611,9.828 3.611,9.846 4.021,9.846 3.929,9.754
  pour cut-out: 3.988,11.747 3.999,11.757 4.229,11.757 4.264,11.721 4.264,11.671 4.064,11.671
  pour cut-out: 4.702,24.768 4.729,24.794 5.625,24.794 5.625,24.711 4.777,24.711
  pour cut-out: 6.925,28.375 7.464,28.375 7.5,28.411 7.5,28.776 7.276,29 6.875,29 6.875,28.575
  pour cut-out: 7.725,31.325 8.075,31.675 8.075,31.75 9.025,31.75 9.05,31.775 8.975,31.85 8.975,32 8.144,32 7.837,31.693 7.753,31.693
  pour cut-out: 8.25,39.75 9.475,39.75 9.475,39.575 8.2,39.575 8.2,39.7 8.275,39.775
  pour cut-out: 17.472,45.391 17.472,38.711 13.472,38.711 13.472,45.391
Signal Layer 6:
  pour cut-out: 19.9,0 19.9,7.5 cw(c20.9,7.5) 20.9,8.5 30.4,8.5 30.4,1.189 cw(c29.211,1.189) 29.211,0
  pour cut-out: 27.88,24.3 27.88,23.572 27.886,23.566 27.886,24.239 27.825,24.3
  pour cut-out: 4.025,15.6 4.025,14.725 3.95,14.8 3.95,15.575
  pour cut-out: 27.886,24.294 27.88,24.3 25.5,24.3 25.625,24.425 27.775,24.425
  pour cut-out: 23.49,32.13 22.38,32.13 22.375,32.125 22.4,32.1 22.4,32.075 23.435,32.075
  pour cut-out: 22.1,34.575 22.05,34.525 22.05,34.3 22,34.3 22.019,34.319 22.019,34.48
  pour cut-out: 23.754,27.786 24.034,27.786 24.281,27.539 24.15,27.408 24.106,27.408 23.754,27.761
  pour cut-out: 23.534,28.989 23.518,28.972 23.518,27.996 23.437,27.996 23.404,28.029 23.404,28.989
  pour cut-out: 23.736,27.829 23.86,27.829 24.207,27.482 24.15,27.425 24.15,27.408 24.106,27.408 23.771,27.743
  pour cut-out: 20.336,26.821 20.35,26.807 20.35,25.45 20.5,25.45 20.575,25.525 20.55,25.55 20.55,26.825
  pour cut-out: 17.475,28.45 17.475,26.85 17.425,26.9 17.375,26.9 17.375,28.4
  pour cut-out: 11.425,27.65 11.425,26.276 11.525,26.376 11.525,27.55
  pour cut-out: 11.475,27.6 11.475,26.943 10.525,26.943 10.525,27.6
  pour cut-out: 4.495,26.047 4.528,26.014 5.221,26.014 5.089,26.146 5.048,26.104 4.569,26.104
  pour cut-out: 3.025,29.65 4.024,29.65 4.044,29.67 4.032,29.682 4.032,29.763 3.088,29.763 3.05,29.725
  region net N16784657: 24.525,10.75 24.525,4.974 27.975,4.974 27.975,5.924 27.975,10.75
  region net N16784657: 2.3,10.45 2.3,4.674 5.75,4.674 5.75,5.624 5.75,10.45
  pour cut-out: 17.472,45.391 17.472,38.711 13.472,38.711 13.472,45.391
Bottom Layer:
  region net GND: 9.209,0.611 cw(c15,7.5) 20.791,0.611 19.325,0.611 19.325,6.8 10.65,6.8 10.65,0.611
  pour cut-out: 19.9,0 19.9,7.5 cw(c20.9,7.5) 20.9,8.5 30.4,8.5 30.4,1.189 cw(c29.211,1.189) 29.211,0
  pour cut-out: 22.597,36.03 22.599,36.032 22.913,36.032 22.913,35.978 22.86,36.03
  pour cut-out: 3.975,22.514 3.975,22.15 4.3,22.15 4.325,22.175 4.275,22.225 4.275,22.6 4.061,22.6
  pour cut-out: 8.524,21.134 8.816,21.134 8.825,21.125 8.825,21.2 8.524,21.2 8.513,21.189
  pour cut-out: 5.62,20.675 5.57,20.625 5.1,20.625 5.1,20.783 5.242,20.925 5.55,20.925
  pour cut-out: 14.4,23.15 14.05,22.8 14.05,22.98 14.215,23.145 14.263,23.096 14.3,23.096
  pour cut-out: 15.815,30.815 14.998,30.815 14.977,30.836 15.752,30.836 15.781,30.866
  pour cut-out: 14.775,29.622 14.775,28.85 14.675,28.85 14.65,28.875 14.682,28.907 14.682,29.634
  pour cut-out: 2.112,33.931 2.112,33.569 2.17,33.569 2.309,33.709 2.171,33.847 2.171,33.889 2.153,33.889
  pour cut-out: 5.631,38.075 5.681,38.025
  pour cut-out: 6.737,38.919 6.737,38.181 6.687,38.232 6.687,38.887 6.705,38.887
  pour cut-out: 4.902,33.673 5.098,33.673 5.098,33.773 5.1,33.775 4.875,33.775 4.902,33.748
  region net N16784657: 2.425,10.45 2.425,4.674 5.75,4.674 5.75,5.624 5.75,10.45
  region net N16784657: 24.525,10.75 24.525,4.959 27.825,4.959 27.825,10.75
  pour cut-out: 7.75,40.05 7.975,40.05 7.975,39.55 7.75,39.55
  pour cut-out: 12.4,19.65 12.8,19.65 12.825,19.625 12.825,18.825 12.4,18.825
  pour cut-out: 12.15,23.375 12.55,23.375 13.1,22.825 12.15,22.825
  pour cut-out: 4.4,20.95 4.4,21.85 5.35,21.85 5.35,20.95
  pour cut-out: 17.472,45.391 17.472,38.711 13.472,38.711 13.472,45.391

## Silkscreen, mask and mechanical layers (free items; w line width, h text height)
Top Overlay:
  lines w0.1: 0,1.2 ccw(c1.2,1.2) 1.2,0 29.2,0 ccw(c29.2,1.2) 30.4,1.2 30.4,44.2 ccw(c29.2,44.2) 29.2,45.4 1.2,45.4 ccw(c1.2,44.2) 0,44.2 0,1.2 ; 23.95,1.1 ccw(c24.35,1.1) 24.35,0.7 ccw(c24.35,1.1) 24.75,1.1 24.75,3.85 26.35,3.85 ccw(c26.35,4.25) 26.75,4.25 ccw(c26.35,4.25) 26.35,4.65 24.35,4.65 ccw(c24.35,4.25) 23.95,4.25 23.95,1.1 ; 27.95,4.25 ccw(c28.337,4.237) 28.325,3.85 29.25,3.85 ccw(c29.25,4.25) 29.65,4.25 ccw(c29.25,4.25) 29.25,4.65 28.35,4.65 ccw(c28.35,4.25) 27.95,4.25
  text "1" at 1.076,35.049 h1.27
  text "EFR32BG27" at 17.818,35.037 h1.5
  text "2" at 28.974,34.975 h1.27
  text "4" at 28.95,32.45 h1.27
  text "3" at 0.946,32.39 h1.27
  text "6" at 28.95,29.939 h1.27
  text "5" at 0.917,29.787 h1.27
  text "LED0" at 16.508,29.284 h1.27
  text "8" at 28.95,27.314 h1.27
  text "7" at 0.899,27.289 h1.27
  text "10" at 28.8,24.864 h1.27
  text "9" at 0.875,24.724 h1.27
  text "12" at 28.818,22.28 h1.27
  text "11" at 0.58,22.191 h1.27
  text "RESET" at 7.07,20.608 h1.27
  text "14" at 28.751,19.895 h1.27
  text "13" at 0.478,19.648 h1.27
  text "16" at 28.775,17.277 h1.27
  text "15" at 0.484,17.11 h1.27
  text "18" at 28.783,14.806 h1.27
  text "17" at 0.519,14.624 h1.27
  text "20" at 28.724,12.164 h1.27
  text "19" at 0.472,12.083 h1.27
  text "BTN0" at 4.324,4.133 h1
  text "J-Link" at 20.509,0.435 h1
Bottom Overlay:
  lines w0.1: 28.35,3.85 28.55,3.85 ; 0,1.2 ccw(c1.2,1.2) 1.2,0 29.2,0 ccw(c29.2,1.2) 30.4,1.2 30.4,44.2 ccw(c29.2,44.2) 29.2,45.4 1.2,45.4 ccw(c1.2,44.2) 0,44.2 0,1.2 ; 23.95,1.1 ccw(c24.35,1.1) 24.35,0.7 ccw(c24.35,1.1) 24.75,1.1 24.75,3.85 26.35,3.85 ccw(c26.35,4.25) 26.75,4.25 ccw(c26.35,4.25) 26.35,4.65 24.35,4.65 ccw(c24.35,4.25) 23.95,4.25 23.95,1.1 ; 27.95,4.25 cw(c28.35,4.25) 28.35,4.65 29.25,4.65 cw(c29.25,4.25) 29.65,4.25 cw(c29.25,4.25) 29.25,3.85 28.325,3.85 cw(c28.337,4.237) 27.95,4.25
  lines w0.152: 10.6,41.56 10.6,40.56 11.6,40.56 ; 10.6,43.61 10.6,44.61 11.6,44.61 ; 20.1,40.56 21.1,40.56 21.1,41.56 ; 20.1,44.61 21.1,44.61 21.1,43.61
  text "BOARD ID" at 9.828,40.521 h1 r270
  text "PCB2602A Rev A01" at 29.025,10.225 h1.52 r270
Top Solder:
  drawing of 9762 lines, arcs and shapes, not listed
  text "L" at 4.91,42.806 h1.25
  text "R" at 28.223,38.872 h1.25
Bottom Solder:
  drawing of 317 lines, arcs and shapes, not listed
BOARD OUTLINE:
  lines w0.076: 30.242,0.594 30.123,0.424 ; 0,1.189 0,44.21 ; 0,1.189 0.02,0.983 ; 0,1.189 0.02,0.983 ; 0,1.189 0,44.21 ; 0,44.21 0.02,44.416 ; 0,44.21 0.02,44.416 ; 0.02,0.983 0.074,0.782 ; 0.02,0.983 0.074,0.782 ; 0.02,44.416 0.074,44.616 ; 0.02,44.416 0.074,44.616 ; 0.074,0.782 0.16,0.594 ; 0.074,0.782 0.16,0.594 ; 0.074,44.616 0.16,44.804 ; 0.074,44.616 0.16,44.804 ; 0.16,0.594 0.279,0.424 ; 0.16,0.594 0.279,0.424 ; 0.16,44.804 0.279,44.974 ; 0.16,44.804 0.279,44.974 ; 0.279,0.424 0.427,0.277 ; 0.279,0.424 0.427,0.277 ; 0.279,44.974 0.427,45.122 ; 0.279,44.974 0.427,45.122 ; 0.427,0.277 0.597,0.16 ; 0.427,0.277 0.597,0.16 ; 0.427,45.122 0.597,45.241 ; 0.427,45.122 0.597,45.241 ; 0.597,0.16 0.785,0.071 ; 0.597,0.16 0.785,0.071 ; 0.597,45.241 0.785,45.328 ; 0.597,45.241 0.785,45.328 ; 0.785,0.071 0.986,0.018 ; 0.785,0.071 0.986,0.018 ; 0.785,45.328 0.986,45.381 ; 0.785,45.328 0.986,45.381 ; 0.986,0.018 1.191,0 ; 0.986,0.018 1.191,0 ; 0.986,45.381 1.191,45.399 ; 0.986,45.381 1.191,45.399 ; 1.191,0 29.211,0 ; 1.191,0 29.211,0 ; 1.191,45.399 29.211,45.399 ; 1.191,45.399 29.211,45.399 ; 29.211,0 29.417,0.018 ; 29.211,0 29.417,0.018 ; 29.211,45.399 29.417,45.381 ; 29.211,45.399 29.417,45.381 ; 29.417,0.018 29.618,0.071 ; 29.417,0.018 29.618,0.071 ; 29.417,45.381 29.618,45.328 ; 29.417,45.381 29.618,45.328 ; 29.618,0.071 29.806,0.16 ; 29.618,0.071 29.806,0.16 ; 29.618,45.328 29.806,45.241 ; 29.618,45.328 29.806,45.241 ; 29.806,0.16 29.976,0.277 ; 29.806,0.16 29.976,0.277 ; 29.806,45.241 29.976,45.122 ; 29.806,45.241 29.976,45.122 ; 29.976,0.277 30.123,0.424 ; 29.976,0.277 30.123,0.424 ; 29.976,45.122 30.123,44.974 ; 29.976,45.122 30.123,44.974 ; 30.123,0.424 30.301,0.678 30.329,0.782 ; 30.123,44.974 30.242,44.804 ; 30.123,44.974 30.242,44.804 ; 30.242,44.804 30.329,44.616 ; 30.242,44.804 30.329,44.616 ; 30.329,0.782 30.382,0.983 ; 30.329,0.782 30.382,0.983 ; 30.329,44.616 30.382,44.416 ; 30.329,44.616 30.382,44.416 ; 30.382,0.983 30.4,1.189 ; 30.382,0.983 30.4,1.189 ; 30.382,44.416 30.4,44.21 ; 30.382,44.416 30.4,44.21 ; 30.4,1.189 30.4,44.21 ; 30.4,1.189 30.4,44.21
  lines w0.1: 23.95,1.1 ccw(c24.35,1.1) 24.35,0.7 ccw(c24.35,1.1) 24.75,1.1 24.75,3.85 26.35,3.85 ccw(c26.35,4.25) 26.75,4.25 ccw(c26.35,4.25) 26.35,4.65 24.35,4.65 ccw(c24.35,4.25) 23.95,4.25 23.95,1.1 ; 27.95,4.25 cw(c28.35,4.25) 28.35,4.65 29.25,4.65 cw(c29.25,4.25) 29.65,4.25 cw(c29.25,4.25) 29.25,3.85 28.325,3.85 cw(c28.337,4.237) 27.95,4.25
  text "Milling 0.8 mm (2 pcs)" at 19.85,5.025 h0.5
Route Tool Path:
  drawing of 355 lines, arcs and shapes, not listed
Top Component Outline (Mech13):
  text "19" at 4.036,11.242 h0.75
  text "20" at 25,11.075 h0.75
Assembly Drawing Frame (Top):
  lines w0.2: -116.788,-25.461 -115.163,-25.461 ; -116.788,21.214 -115.163,21.214 ; -116.788,67.889 -115.163,67.889 ; -62.138,-73.711 -62.138,-72.111 ; -62.138,114.589 -62.138,116.189 ; -9.113,-73.711 -9.113,-72.111 ; -9.113,114.589 -9.113,116.189 ; 43.912,-73.711 43.912,-72.111 ; 43.912,114.589 43.912,116.189 ; 96.937,-73.711 96.937,-72.111 ; 96.937,114.589 96.937,116.189 ; 149.962,-25.436 151.587,-25.436 ; 149.962,21.239 151.587,21.239 ; 149.962,67.914 151.587,67.914 ; 151.587,-73.711 -116.788,-73.711 -116.788,116.189 151.587,116.189 151.587,-73.686 ; -115.163,-72.111 -115.163,114.589 149.962,114.589 149.962,-72.111 -115.163,-72.111
  text "5" at -89.815,115.218 h0.5
  text "2" at 70.069,115.203 h0.5
  text "1" at 125.891,115.208 h0.5
  text "4" at -36.151,115.108 h0.5
  text "3" at 18.837,115.108 h0.5
  text "D" at 150.677,91.148 h0.5
  text "D" at -116.135,91.028 h0.5
  text "C" at 150.585,44.782 h0.5
  text "C" at -116.207,44.714 h0.5
  text "B" at 150.769,-1.86 h0.5
  text "B" at -116.047,-2.634 h0.5
  text "A" at 150.677,-47.505 h0.5
  text "A" at -116.163,-48.538 h0.5
  text "3" at 19.231,-73.102 h0.5
  text "4" at -33.651,-73.13 h0.5
  text "2" at 71.068,-73.127 h0.5
  text "1" at 125.969,-73.176 h0.5
  text "5" at -89.861,-73.206 h0.5
Title Block (Top):
  drawing of 27 lines, arcs and shapes, not listed
  text "Board Title" at 80.362,-47.161 h2.5
  text "EFR32BG27 +8 dBm DK" at 81.762,-52.711 h3.5
  text "Page Title" at 80.362,-56.886 h2.5
  text "Designed:" at 48.112,-60.636 h1.7
  text "Approved:" at 64.312,-60.636 h1.7
  text "Top Assembly" at 81.762,-60.786 h3.2
  text "KIM" at 49.637,-63.136 h2.2
  text "PEP" at 65.687,-63.136 h2.2
  text "Revision" at 138.262,-63.911 h1.7
  text "Document number" at 80.362,-64.186 h2.35
  text "Size" at 48.112,-65.386 h1.7
  text "Sheet Modified Date" at 53.037,-65.386 h1.7
  text "A01" at 138.537,-66.961 h2.7
  text "BRD2602A (PCB2602A Rev A01)" at 81.762,-67.061 h3.2
  text "A4" at 48.687,-67.236 h2
  text "'.Print_Date'" at 53.612,-67.236 h2
  text "Sheet" at 138.262,-69.586 h1.7
  text "COPYRIGHT SILICON LABORATORIES  INC. 2022" at 52.759,-70.594 h1.7
  text "CONFIDENTIAL -SUBJECT TO TERMS OF USE" at 92.741,-70.594 h1.7
  text "1" at 139.462,-71.536 h1.7
  text "of" at 142.587,-71.536 h1.7
  text "2" at 145.312,-71.536 h1.7
Assembly Drawing Frame (Bottom):
  lines w0.2: -116.788,-25.461 -115.163,-25.461 ; -116.788,21.214 -115.163,21.214 ; -116.788,67.889 -115.163,67.889 ; -62.138,-73.711 -62.138,-72.111 ; -62.138,114.589 -62.138,116.189 ; -9.113,-73.711 -9.113,-72.111 ; -9.113,114.589 -9.113,116.189 ; 43.912,-73.711 43.912,-72.111 ; 43.912,114.589 43.912,116.189 ; 96.937,-73.711 96.937,-72.111 ; 96.937,114.589 96.937,116.189 ; 149.962,-25.436 151.587,-25.436 ; 149.962,21.239 151.587,21.239 ; 149.962,67.914 151.587,67.914 ; 151.587,-73.711 -116.788,-73.711 -116.788,116.189 151.587,116.189 151.587,-73.686 ; -115.163,-72.111 -115.163,114.589 149.962,114.589 149.962,-72.111 -115.163,-72.111
  text "5" at -89.416,115.277 h0.5
  text "2" at 70.414,115.218 h0.5
  text "1" at 126.048,115.212 h0.5
  text "4" at -35.784,115.146 h0.5
  text "3" at 19.188,115.115 h0.5
  text "D" at 150.971,91.183 h0.5
  text "D" at -115.793,90.988 h0.5
  text "D" at -115.793,90.988 h0.5
  text "C" at -115.898,44.779 h0.5
  text "C" at 150.91,44.777 h0.5
  text "B" at 151.064,-1.852 h0.5
  text "B" at -115.755,-2.602 h0.5
  text "A" at 150.985,-47.498 h0.5
  text "A" at -115.827,-48.519 h0.5
  text "3" at 19.568,-73.078 h0.5
  text "2" at 71.424,-73.135 h0.5
  text "4" at -33.348,-73.15 h0.5
  text "1" at 126.156,-73.162 h0.5
  text "5" at -89.509,-73.211 h0.5
Title Block (Bottom):
  drawing of 27 lines, arcs and shapes, not listed
  text "Board Title" at -45.563,-47.161 h2.5
  text "EFR32BG27 +8 dBm DK" at -46.963,-52.711 h3.5
  text "Page Title" at -45.563,-56.886 h2.5
  text "Approved:" at -29.513,-60.636 h1.7
  text "Designed:" at -13.313,-60.636 h1.7
  text "Bottom Assembly" at -46.963,-60.786 h3.2
  text "PEP" at -30.888,-63.136 h2.2
  text "KIM" at -14.838,-63.136 h2.2
  text "Revision" at -103.463,-63.911 h1.7
  text "Document number" at -45.563,-64.186 h2.35
  text "Sheet Modified Date" at -18.238,-65.386 h1.7
  text "Size" at -13.313,-65.386 h1.7
  text "A01" at -103.727,-66.961 h2.7
  text "BRD2602A (PCB2602A Rev A01)" at -46.963,-67.061 h3.2
  text "'.Print_Date'" at -18.813,-67.236 h2
  text "A4" at -13.888,-67.236 h2
  text "Sheet" at -103.463,-69.586 h1.7
  text "COPYRIGHT SILICON LABORATORIES  INC. 2022" at -18.075,-70.522 h1.7
  text "CONFIDENTIAL -SUBJECT TO TERMS OF USE" at -58.639,-70.61 h1.7
  text "2" at -110.513,-71.536 h1.7
  text "of" at -107.788,-71.536 h1.7
  text "2" at -104.663,-71.536 h1.7
Assembly Drawing Frame:
  lines w0.2: -124.351,-78.859 159.149,-78.859 159.149,121.616 -124.351,121.616 -124.351,-78.859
